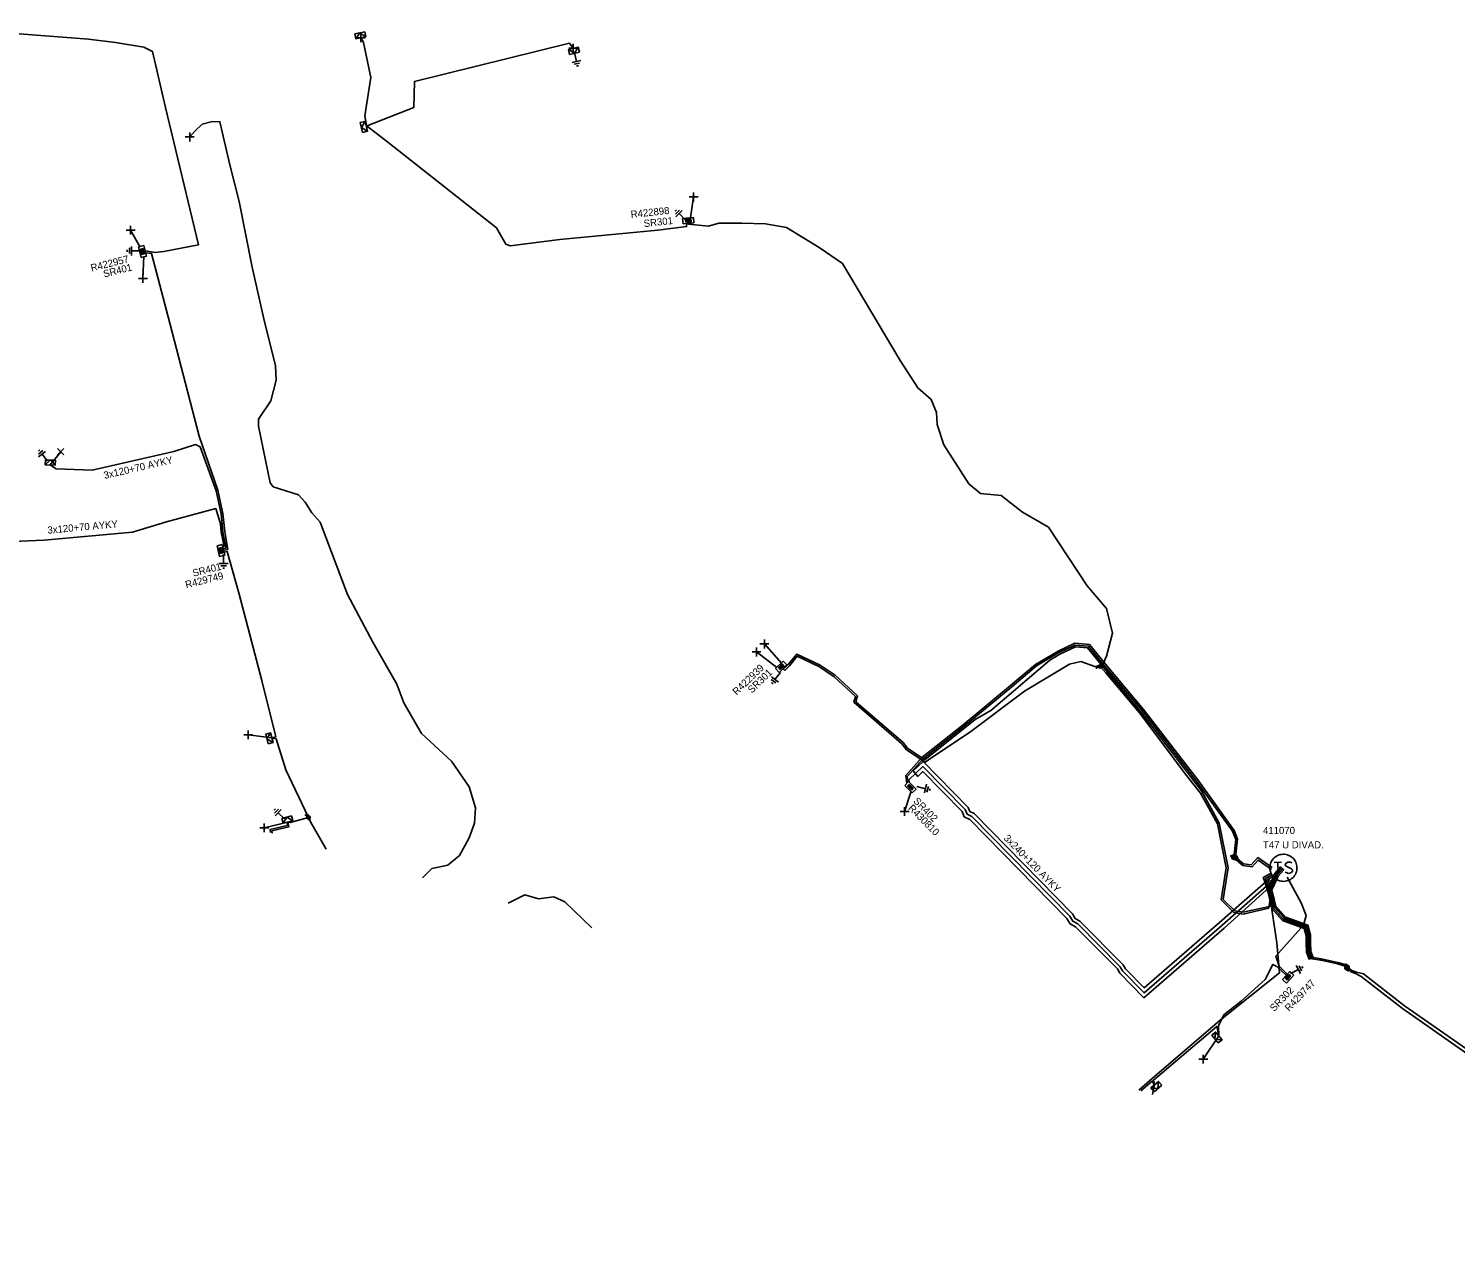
# Model space of a CAD drawing. Extents: x -540247 to -537390, y -1183890 to -1180355.
# Drawn here: x -537806.3 to -537607.2, y -1180801 to -1180629.3 of the extents above; entities that cross this region are included whole.
import ezdxf

# ---------------------------------------------------------------- set-up
doc = ezdxf.new("R2010")
doc.units = 0
for name, color, linetype in [('Vrstva 1', 7, 'Continuous'), ('Vrstva 14', 7, 'Continuous'), ('Vrstva 15', 7, 'Continuous'), ('Vrstva 19', 7, 'Continuous'), ('Vrstva 20', 7, 'Continuous'), ('Vrstva 25', 7, 'Continuous'), ('Vrstva 26', 7, 'Continuous'), ('Vrstva 27', 7, 'Continuous'), ('Vrstva 28', 7, 'Continuous'), ('Vrstva 29', 7, 'Continuous'), ('Vrstva 30', 7, 'Continuous'), ('Vrstva 31', 7, 'Continuous'), ('Vrstva 34', 7, 'Continuous'), ('Vrstva 4', 7, 'Continuous'), ('Vrstva 5', 7, 'Continuous'), ('Vrstva 52', 7, 'Continuous'), ('Vrstva 59', 7, 'Continuous'), ('Vrstva 6', 7, 'Continuous'), ('Vrstva 8', 7, 'Continuous'), ('Vrstva 9', 7, 'Continuous')]:
    doc.layers.add(name, color=color, linetype=linetype)

# ---------------------------------------------------------------- blocks, each defined once
blk = doc.blocks.new('NN870')
at = {"layer": 'Vrstva 4'}
for points in [[(0, -0.25), (0.5, 0), (0, 0.25), (-0.5, 0), (0, -0.25)], [(0.37, 0), (0, 0.19), (-0.36, 0), (0, -0.19), (0.37, 0)], [(0.24, 0), (0, 0.12), (-0.25, 0), (0, -0.12), (0.24, 0)], [(0.12, 0), (0, 0.06), (-0.13, 0), (0, -0.06), (0.12, 0)]]:
    blk.add_lwpolyline(points, dxfattribs=at)
blk = doc.blocks.new('NN880')
at = {"layer": 'Vrstva 4'}
for points in [[(0, 0.25), (-0.5, 0)], [(0, 0.18), (-0.37, 0)], [(0, 0.12), (-0.25, 0)], [(0, 0.06), (-0.12, 0)], [(0.5, 0), (0, 0.25)], [(0.38, 0), (0, 0.18)], [(0.25, 0), (0, 0.12)], [(0.13, 0), (0, 0.06)], [(-0.57, -0.13), (-0.44, -0.13)], [(-0.5, 0), (0, -0.25)], [(-0.5, -0.13), (-0.5, -0.33)], [(-0.37, 0), (0, -0.19)], [(-0.25, 0), (0, -0.13)], [(-0.12, 0), (0, -0.06)], [(0, -0.25), (0.5, 0)], [(0, -0.19), (0.38, 0)], [(0, -0.13), (0.25, 0)], [(0, -0.06), (0.13, 0)]]:
    blk.add_lwpolyline(points, dxfattribs=at)
blk = doc.blocks.new('NN800')
at = {"layer": 'Vrstva 1'}
for points in [[(-0.44, 0.44), (0.44, -0.44)], [(-0.44, -0.44), (0.44, 0.44)]]:
    blk.add_lwpolyline(points, dxfattribs=at)
blk = doc.blocks.new('NN620')
at = {"layer": 'Vrstva 8'}
for points in [[(0.75, 0), (-0.75, 0)], [(-0.75, 0), (-0.75, -0.75)], [(0.75, -0.75), (0.75, 0)], [(-0.75, -0.75), (0.75, -0.75)], [(0.37, -0.18), (-0.38, -0.18)], [(-0.38, -0.18), (-0.38, -0.56)], [(-0.38, -0.56), (0.37, -0.56)], [(0.32, -0.23), (-0.33, -0.23)], [(-0.33, -0.23), (-0.33, -0.51)], [(-0.33, -0.51), (0.32, -0.51)], [(0.27, -0.27), (-0.28, -0.27)], [(-0.28, -0.27), (-0.28, -0.46)], [(-0.28, -0.46), (0.27, -0.46)], [(0.23, -0.32), (-0.23, -0.32)], [(-0.23, -0.32), (-0.23, -0.42)], [(-0.23, -0.42), (0.23, -0.42)], [(-0.19, -0.37), (0.19, -0.37)], [(0.23, -0.42), (0.23, -0.32)], [(0.27, -0.46), (0.27, -0.27)], [(0.32, -0.51), (0.32, -0.23)], [(0.37, -0.56), (0.37, -0.18)]]:
    blk.add_lwpolyline(points, dxfattribs=at)
blk = doc.blocks.new('NN630')
at = {"layer": 'Vrstva 9'}
for points in [[(0, -0.7), (-0.7, 0)], [(-0.7, -0.7), (-0.7, 0), (0.7, 0), (0.7, -0.7)], [(-0.7, -0.7), (0.7, -0.7)], [(0, -0.7), (0.7, 0)]]:
    blk.add_lwpolyline(points, dxfattribs=at)
blk = doc.blocks.new('NN810')
at = {"layer": 'Vrstva 14'}
for points in [[(0.63, -1.89), (-0.62, -1.89)], [(0, -0.64), (0, -1.89)], [(0.39, -2.2), (-0.4, -2.2)], [(0, -2.52), (-0.12, -2.52)], [(0.14, -2.52), (0, -2.52)]]:
    blk.add_lwpolyline(points, dxfattribs=at)
blk = doc.blocks.new('NN610')
at = {"layer": 'Vrstva 6'}
for points in [[(1.88, 0), (1.87, 0.2), (1.84, 0.39), (1.79, 0.58), (1.72, 0.77), (1.63, 0.94), (1.52, 1.11), (1.4, 1.26), (1.26, 1.4), (1.1, 1.53), (0.94, 1.63), (0.76, 1.72), (0.58, 1.8), (0.19, 1.88), (0.19, 1.88), (-0.01, 1.89), (-0.21, 1.88), (-0.4, 1.85), (-0.59, 1.8), (-0.78, 1.72), (-0.95, 1.63), (-1.12, 1.53), (-1.27, 1.4), (-1.41, 1.26), (-1.54, 1.11), (-1.64, 0.94), (-1.73, 0.77), (-1.8, 0.58), (-1.86, 0.39), (-1.89, 0.2), (-1.9, 0), (-1.89, -0.2), (-1.86, -0.39), (-1.8, -0.58), (-1.73, -0.77), (-1.64, -0.95), (-1.54, -1.11), (-1.41, -1.27), (-1.27, -1.41), (-1.12, -1.53), (-0.95, -1.64), (-0.78, -1.73), (-0.59, -1.8), (-0.4, -1.85), (-0.21, -1.88), (-0.01, -1.89), (0.19, -1.88), (0.39, -1.85), (0.58, -1.8), (0.76, -1.73), (0.94, -1.64), (1.1, -1.53), (1.26, -1.41), (1.4, -1.27), (1.52, -1.11), (1.63, -0.95), (1.72, -0.77), (1.79, -0.58), (1.84, -0.39), (1.87, -0.2), (1.88, 0)], [(-1.27, 0.78), (-0.26, 0.78)], [(-0.76, 0.78), (-0.76, -0.79)], [(1.19, 0.66), (0.94, 0.78), (0.62, 0.78), (0.37, 0.66), (0.24, 0.47), (0.24, 0.4), (0.37, 0.22), (1.12, -0.16), (1.25, -0.32), (1.25, -0.48), (1.12, -0.67), (0.87, -0.79), (0.62, -0.79), (0.49, -0.73), (0.24, -0.6)]]:
    blk.add_lwpolyline(points, dxfattribs=at)

msp = doc.modelspace()

# ---------------------------------------------------------------- linework, layer by layer
at = {"layer": 'Vrstva 20'}
for points in [[(-537633.23, -1180747.94), (-537632.64, -1180748.61), (-537639.46, -1180754.77), (-537650.67, -1180764.5), (-537654.04, -1180761.05), (-537654.36, -1180760.48), (-537660.2, -1180754.59), (-537660.96, -1180754.18), (-537661.41, -1180753.42), (-537674.95, -1180739.6), (-537675.72, -1180739.24), (-537676.02, -1180738.52), (-537681.5, -1180732.94), (-537682.2, -1180733.6), (-537682.88, -1180732.83), (-537681.48, -1180731.54), (-537675.17, -1180737.96), (-537674.94, -1180738.5), (-537674.36, -1180738.78), (-537660.61, -1180752.8), (-537660.24, -1180753.44), (-537659.6, -1180753.79), (-537653.56, -1180759.88), (-537653.24, -1180760.45), (-537650.61, -1180763.12), (-537640.12, -1180754.01)], [(-537627.07, -1180758.89), (-537627.63, -1180759.1), (-537628, -1180758.14), (-537628.03, -1180756.82), (-537628.02, -1180755.87), (-537628.29, -1180754.83), (-537631.34, -1180753.71), (-537632.84, -1180752.04), (-537633.42, -1180749.37), (-537632.7, -1180747.79), (-537632.45, -1180747.22), (-537631.61, -1180746.24), (-537631.15, -1180746.64), (-537631.93, -1180747.54), (-537632.16, -1180748.03), (-537632.8, -1180749.43), (-537632.28, -1180751.76), (-537631, -1180753.19), (-537627.79, -1180754.37), (-537627.42, -1180755.77), (-537627.43, -1180756.79), (-537627.4, -1180758.02)]]:
    msp.add_lwpolyline(points, close=True, dxfattribs=at)
at = {"layer": 'Vrstva 5'}
for points in [[(-537818.04, -1180631.5), (-537818.12, -1180630.22), (-537817.28, -1180629.26), (-537797.92, -1180630.76), (-537794.16, -1180631.22), (-537790.18, -1180631.86), (-537788.96, -1180632.47), (-537787.17, -1180640.3), (-537782.56, -1180659.43), (-537787.39, -1180660.39), (-537788.61, -1180660.5), (-537789.99, -1180660.28)], [(-537783.09, -1180643.59), (-537782.07, -1180642.62), (-537780.61, -1180642.22), (-537779.58, -1180642.27), (-537778.18, -1180648.3), (-537776.88, -1180653.38), (-537775.06, -1180662.55), (-537773.45, -1180669.78), (-537771.84, -1180676.34), (-537771.71, -1180678.32), (-537772.45, -1180681.2), (-537774.2, -1180683.78), (-537774.17, -1180684.72), (-537772.56, -1180692.63), (-537772.13, -1180693.2), (-537768.63, -1180694.32), (-537767.68, -1180695.35), (-537766.74, -1180696.81), (-537765.6, -1180698.14), (-537761.76, -1180708.24), (-537758.24, -1180714.9), (-537754.88, -1180720.76), (-537753.92, -1180723.34), (-537751.43, -1180727.62), (-537747.25, -1180731.49), (-537744.82, -1180735.04), (-537743.92, -1180738.01), (-537744.06, -1180740.11), (-537744.78, -1180742.18), (-537746.13, -1180744.64), (-537747.77, -1180745.97), (-537750, -1180746.48), (-537751.29, -1180747.74)], [(-537714.45, -1180656.49), (-537714.46, -1180656.89), (-537718.48, -1180657.39), (-537732.15, -1180658.69), (-537739.1, -1180659.6), (-537739.7, -1180659.35), (-537741, -1180657.05), (-537756.17, -1180645.11), (-537758.98, -1180642.94), (-537759.15, -1180642.9)], [(-537656.79, -1180718.27), (-537656.53, -1180718.26), (-537655.89, -1180716.82), (-537655.04, -1180713.63), (-537655.89, -1180710.2), (-537658.59, -1180707.01), (-537663.98, -1180698.82), (-537667.6, -1180696.73), (-537670.58, -1180694.42), (-537673.47, -1180694.14), (-537675.09, -1180692.79), (-537678.56, -1180687.36), (-537679.5, -1180684.49), (-537679.62, -1180682.84), (-537680.35, -1180681.01), (-537682.22, -1180679.41), (-537684.65, -1180675.6), (-537692.7, -1180662.05), (-537695.95, -1180659.82), (-537700.51, -1180657.04), (-537703.47, -1180656.49), (-537706.77, -1180656.42), (-537709.99, -1180656.4), (-537711.42, -1180656.82), (-537714.2, -1180656.56), (-537714.2, -1180656.46)], [(-537779.03, -1180702.05), (-537778.45, -1180701.94), (-537778.9, -1180699.46), (-537779.15, -1180696.92), (-537779.88, -1180693.68), (-537782.47, -1180686.13), (-537786.58, -1180670.35), (-537789.1, -1180660.67), (-537789.92, -1180660.55)], [(-537779.09, -1180701.81), (-537778.71, -1180701.74), (-537779.15, -1180699.51), (-537779.39, -1180696.96), (-537780.12, -1180693.74), (-537782.34, -1180687.61), (-537782.99, -1180687.31), (-537786, -1180688.26), (-537797.4, -1180690.89), (-537802.41, -1180690.69), (-537802.93, -1180690.38), (-537803.26, -1180690.15)], [(-537779.15, -1180701.57), (-537779, -1180701.54), (-537779.4, -1180699.55), (-537779.5, -1180698.39), (-537780.16, -1180696.25), (-537787.04, -1180698.11), (-537791.79, -1180699.52), (-537804.08, -1180700.65), (-537807.4, -1180700.78), (-537812.42, -1180701.23), (-537816.61, -1180701.32), (-537820.02, -1180701.24), (-537824.76, -1180700.45), (-537825.15, -1180700.38)], [(-537767.23, -1180739.35), (-537770.39, -1180732.71), (-537771.75, -1180728.35), (-537772.33, -1180728.21), (-537771.79, -1180728.11), (-537773.73, -1180720.25), (-537776.91, -1180708.2), (-537778.57, -1180702.22), (-537778.97, -1180702.3)], [(-537632.88, -1180747.39), (-537633.72, -1180747.86), (-537632.77, -1180750.69), (-537632.95, -1180751.7), (-537636.81, -1180752.55), (-537637.99, -1180752.37), (-537639.61, -1180750.76), (-537638.91, -1180746.38), (-537640.15, -1180740.14), (-537642.62, -1180735.61), (-537651.09, -1180724.59), (-537656.44, -1180718.25), (-537658.52, -1180715.67), (-537660.2, -1180715.53), (-537662.41, -1180716.56), (-537663.77, -1180717.39), (-537672.03, -1180724.4), (-537674.19, -1180725.68), (-537681.23, -1180731.3), (-537683.64, -1180729.69), (-537684.27, -1180728.9), (-537690.84, -1180723.19), (-537690.63, -1180722.38), (-537693.74, -1180719.5), (-537695.82, -1180718.08), (-537699.1, -1180716.55), (-537700.31, -1180718), (-537700.77, -1180718.47), (-537700.81, -1180718.43)], [(-537632.76, -1180746.32), (-537634.78, -1180744.94), (-537635.7, -1180745.94), (-537636.76, -1180745.82), (-537637.88, -1180744.86), (-537637.6, -1180742.35), (-537638.07, -1180741.15), (-537643.02, -1180734.27), (-537650.7, -1180724.28), (-537656.04, -1180717.95), (-537658.26, -1180715.19), (-537660.29, -1180715.03), (-537662.65, -1180716.12), (-537665.8, -1180717.98), (-537669.27, -1180720.91), (-537675.89, -1180726.39), (-537681.64, -1180730.96), (-537683.88, -1180733.46), (-537683.74, -1180734.57)], [(-537632.87, -1180746.58), (-537634.74, -1180745.28), (-537635.56, -1180746.21), (-537636.86, -1180746.06), (-537638.14, -1180744.96), (-537637.86, -1180742.39), (-537638.3, -1180741.27), (-537643.22, -1180734.42), (-537650.9, -1180724.43), (-537656.24, -1180718.1), (-537658.39, -1180715.43), (-537660.24, -1180715.28), (-537662.53, -1180716.34), (-537665.64, -1180718.18), (-537669.09, -1180721.09), (-537675.75, -1180726.6), (-537681.47, -1180731.14), (-537683.7, -1180733.64), (-537683.59, -1180734.43)], [(-537700.98, -1180718.6), (-537700.77, -1180718.82), (-537700.13, -1180718.16), (-537699.04, -1180716.85), (-537695.94, -1180718.3), (-537693.9, -1180719.7), (-537690.91, -1180722.46), (-537691.12, -1180723.27), (-537684.45, -1180729.08), (-537683.8, -1180729.89), (-537681.18, -1180731.6), (-537680.25, -1180730.99), (-537675.01, -1180727.5), (-537667.34, -1180721.71), (-537661.07, -1180717.96), (-537659.46, -1180717.58), (-537657.53, -1180718.29), (-537656.79, -1180718.27)], [(-537656.79, -1180718.27), (-537656, -1180719.17), (-537651.3, -1180724.73), (-537648.46, -1180728.51), (-537644.91, -1180733.23), (-537642.75, -1180735.93), (-537640.39, -1180740.22), (-537639.17, -1180746.38), (-537639.87, -1180750.84), (-537638.11, -1180752.61), (-537636.81, -1180752.81), (-537633.26, -1180752), (-537633.03, -1180750.7), (-537633.85, -1180748.16), (-537634.02, -1180747.73), (-537632.93, -1180747.1)], [(-537632.59, -1180747.81), (-537632.72, -1180748.16), (-537639.79, -1180754.39), (-537650.64, -1180763.81), (-537653.64, -1180760.75), (-537653.96, -1180760.18), (-537659.9, -1180754.19), (-537660.6, -1180753.81), (-537661.01, -1180753.11), (-537674.66, -1180739.19), (-537675.33, -1180738.87), (-537675.59, -1180738.24), (-537681.49, -1180732.24), (-537683.47, -1180734.09), (-537683.43, -1180734.4)], [(-537770.08, -1180739.98), (-537769.78, -1180740.03), (-537767.23, -1180739.35)], [(-537764.76, -1180743.74), (-537766.95, -1180739.93), (-537767.23, -1180739.35)], [(-537631.46, -1180746.37), (-537632.28, -1180747.33), (-537632.52, -1180747.87), (-537633.21, -1180749.39), (-537632.65, -1180751.95), (-537631.23, -1180753.54), (-537628.12, -1180754.68), (-537627.82, -1180755.84), (-537627.84, -1180756.78), (-537627.81, -1180758.1), (-537627.45, -1180759.03), (-537625.76, -1180759.3), (-537623.67, -1180759.76), (-537622.58, -1180760.08), (-537622.41, -1180760.33)], [(-537631.3, -1180746.51), (-537632.1, -1180747.43), (-537632.34, -1180747.95), (-537633.01, -1180749.41), (-537632.47, -1180751.85), (-537631.11, -1180753.36), (-537627.96, -1180754.52), (-537627.62, -1180755.8), (-537627.64, -1180756.77), (-537627.61, -1180758.06), (-537627.3, -1180758.85), (-537625.72, -1180759.1), (-537623.63, -1180759.56), (-537622.46, -1180759.9), (-537622.25, -1180760.23)], [(-537651.39, -1180777.39), (-537649.52, -1180775.76), (-537640.04, -1180767.63), (-537631.75, -1180761.02), (-537632.1, -1180756.84), (-537632.8, -1180752.16), (-537632.51, -1180750.67), (-537633.39, -1180747.96), (-537632.74, -1180747.6)], [(-537630.69, -1180747.68), (-537628.72, -1180751.24), (-537628.02, -1180753.03), (-537628.4, -1180754.35), (-537632.25, -1180758.7), (-537631.8, -1180760.09), (-537630.66, -1180761.18)], [(-537739.36, -1180751.28), (-537737.03, -1180750.12), (-537735.13, -1180750.68), (-537732.98, -1180750.39), (-537731.46, -1180751.11), (-537727.7, -1180754.74)], [(-537651.09, -1180777.49), (-537649.51, -1180776.13), (-537649.17, -1180776.62), (-537649.31, -1180775.99), (-537640.51, -1180768.5), (-537640.22, -1180769.81), (-537640.28, -1180768.39), (-537639.51, -1180766.88), (-537637.08, -1180764.96), (-537633.76, -1180761.96), (-537632.67, -1180759.83), (-537632.13, -1180760.12), (-537630.83, -1180761.36)], [(-537539.27, -1180800.97), (-537540.33, -1180800.01), (-537540.77, -1180798.09), (-537554.14, -1180795.43), (-537572.94, -1180789.46), (-537579.99, -1180786.34), (-537583.4, -1180794.6), (-537583.56, -1180794.69), (-537583.6, -1180794.52), (-537580.17, -1180786.23), (-537584.61, -1180784.3), (-537592.51, -1180779.99), (-537605.42, -1180772.39), (-537614.61, -1180766.01), (-537620.35, -1180761.52), (-537621.15, -1180761.13), (-537621.78, -1180760.86), (-537622.41, -1180760.33)], [(-537539, -1180801.01), (-537538.98, -1180800.82), (-537539.87, -1180799.75), (-537540.35, -1180797.67), (-537554.02, -1180794.95), (-537572.76, -1180789), (-537584.39, -1180783.86), (-537592.27, -1180779.55), (-537605.16, -1180771.97), (-537614.31, -1180765.61), (-537620.03, -1180761.14), (-537621, -1180760.93), (-537621.67, -1180760.69), (-537622.25, -1180760.23)]]:
    msp.add_lwpolyline(points, dxfattribs=at)
at = {"layer": 'Vrstva 52'}
for points in [[(-537759.15, -1180642.9), (-537759.13, -1180642.81), (-537759.34, -1180641.45), (-537758.53, -1180636.07), (-537759.53, -1180631.21), (-537759.92, -1180630.54)], [(-537770.08, -1180739.98), (-537773.38, -1180740.78)], [(-537770.08, -1180739.98), (-537770.2, -1180740.45), (-537772.57, -1180741.03), (-537772.5, -1180741.44)], [(-537770.08, -1180739.98), (-537769.97, -1180740.65), (-537772.32, -1180741.22), (-537772.27, -1180741.51)]]:
    msp.add_lwpolyline(points, dxfattribs=at)
at = {"layer": 'Vrstva 59'}
for points in [[(-537759.15, -1180642.9), (-537752.53, -1180640.3), (-537752.42, -1180636.63), (-537730.81, -1180631.28), (-537730.27, -1180632.02)], [(-537783.09, -1180643.59), (-537783.78, -1180644.39)], [(-537713.9, -1180655.68), (-537713.49, -1180652.75)], [(-537790.68, -1180659.75), (-537792.03, -1180657.39)], [(-537790.21, -1180661.05), (-537790.31, -1180664.12)], [(-537803.26, -1180690.15), (-537801.79, -1180688.31)], [(-537701.23, -1180717.79), (-537703.61, -1180715.12)], [(-537701.86, -1180718.41), (-537704.72, -1180716.25)], [(-537772.33, -1180728.21), (-537775.63, -1180727.81)], [(-537683.14, -1180735.68), (-537684.06, -1180738.5)], [(-537640.22, -1180769.81), (-537642.39, -1180773.06)], [(-537649.17, -1180776.62), (-537649.45, -1180777.97)]]:
    msp.add_lwpolyline(points, dxfattribs=at)

# ---------------------------------------------------------------- block references
at = {"layer": 'Vrstva 15'}
for p, rotation in [((-537730.27, -1180632.02), 13.178672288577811), ((-537714.19, -1180656.43), -135.2424277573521), ((-537790.01, -1180660.28), -90), ((-537803.26, -1180690.15), -143.0495916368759), ((-537701, -1180718.58), -37.20250280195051), ((-537682.97, -1180734.86), 75.84293605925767), ((-537770.08, -1180739.97), -133.39412490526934), ((-537630.81, -1180761.38), 116.60259170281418)]:
    msp.add_blockref('NN810', p, dxfattribs=dict(at, rotation=rotation))
msp.add_blockref('NN810', (-537779.07, -1180702.01), dxfattribs=at)
at = {"layer": 'Vrstva 19'}
for name, p, rotation in [('NN880', (-537656.79, -1180718.27), 1.6640749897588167), ('NN880', (-537767.23, -1180739.35), -64.3525611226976), ('NN870', (-537638.14, -1180744.96), -40.645536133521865), ('NN870', (-537637.88, -1180744.86), -40.66437214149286), ('NN870', (-537622.41, -1180760.33), 121.52541101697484), ('NN870', (-537622.25, -1180760.23), 120.45509796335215)]:
    msp.add_blockref(name, p, dxfattribs=dict(at, rotation=rotation))
at = {"layer": 'Vrstva 25', "rotation": 1.2181833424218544}
msp.add_blockref('NN610', (-537631.19, -1180746.36), dxfattribs=at)
at = {"layer": 'Vrstva 28'}
for p, rotation in [((-537714.19, -1180656.43), -173.77038606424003), ((-537790.01, -1180660.28), -75.89639448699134), ((-537779.07, -1180702), -75.89639448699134), ((-537701, -1180718.58), -135.88956381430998), ((-537682.97, -1180734.86), -45.24242780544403), ((-537630.81, -1180761.38), 46.60608053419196)]:
    msp.add_blockref('NN620', p, dxfattribs=dict(at, rotation=rotation))
at = {"layer": 'Vrstva 31'}
for p, rotation in [((-537759.92, -1180630.54), -168.23326667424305), ((-537730.26, -1180632.02), 13.178672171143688), ((-537759.15, -1180642.9), -76.32872222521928), ((-537803.26, -1180690.15), 177.5015768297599), ((-537772.33, -1180728.21), -75.33864996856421), ((-537770.08, -1180739.98), -165.87760275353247), ((-537640.22, -1180769.81), -49.68453604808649), ((-537649.17, -1180776.62), 40.940808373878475)]:
    msp.add_blockref('NN630', p, dxfattribs=dict(at, rotation=rotation))
at = {"layer": 'Vrstva 34', "rotation": 45}
for p in [(-537759.92, -1180630.54), (-537730.27, -1180632.02), (-537783.78, -1180644.39), (-537713.49, -1180652.75), (-537792.03, -1180657.39), (-537790.31, -1180664.12), (-537704.72, -1180716.25), (-537703.61, -1180715.12), (-537775.63, -1180727.81), (-537684.06, -1180738.5), (-537773.38, -1180740.78), (-537642.39, -1180773.06)]:
    msp.add_blockref('NN800', p, dxfattribs=at)
at = {"layer": 'Vrstva 34'}
msp.add_blockref('NN800', (-537801.79, -1180688.31), dxfattribs=at)

# ---------------------------------------------------------------- texts
at = {"layer": 'Vrstva 26'}
msp.add_text('411070', height=1, dxfattribs=at).set_placement((-537634.05, -1180741.65))
at = {"layer": 'Vrstva 27'}
msp.add_text('T47 U DIVAD.', height=1, dxfattribs=at).set_placement((-537634.05, -1180743.65))
at = {"layer": 'Vrstva 29'}
for s, rotation, p in [('R422898', 6.23, (-537722.21, -1180655.7)), ('R422957', 14.104, (-537797.47, -1180663.17)), ('R429749', 14.104, (-537784.27, -1180707.36)), ('R422939', 44.11, (-537707.48, -1180722.35)), ('R430810', 314.758, (-537683.63, -1180738.12)), ('R429747', 46.606, (-537630.4, -1180766.47))]:
    msp.add_text(s, height=1, rotation=rotation, dxfattribs=at).set_placement(p)
at = {"layer": 'Vrstva 30'}
for s, rotation, p in [('SR301', 6.23, (-537720.4, -1180656.97)), ('SR401', 14.104, (-537795.71, -1180664)), ('SR401', 14.104, (-537783.26, -1180705.75)), ('SR301', 44.11, (-537705.36, -1180722.07)), ('SR402', 314.758, (-537682.91, -1180737.14)), ('SR302', 46.606, (-537632.48, -1180766.49))]:
    msp.add_text(s, height=1, rotation=rotation, dxfattribs=at).set_placement(p)
at = {"layer": 'Vrstva 6'}
for s, rotation, p in [('3x120+70 AYKY', 12.975, (-537795.67, -1180692.11)), ('3x120+70 AYKY', 5.253, (-537803.59, -1180699.75)), ('3x240+120 AYKY', 314.439, (-537670.31, -1180742.32))]:
    msp.add_text(s, height=1, rotation=rotation, dxfattribs=at).set_placement(p)

doc.saveas('drawing.dxf')
